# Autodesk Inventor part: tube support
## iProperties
Created: 2002-09
Part Number: tube support
Material: Par défaut
Document SubType Name: Modélisation
Designer: Maison
Control State: 0
Master: False
Checked Out: False
Shininess: 37.0
Length Units: 11269
Angle Units: 11279
Time Units: 11290
Mass Units: 11283
Length Display Precision: 3
Angle Display Precision: 2
Density: 0.0
Volumn: 0.0
Area: 0.0
PropertySet Name: Model Information
Author: Maison
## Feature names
1. Balayage1
